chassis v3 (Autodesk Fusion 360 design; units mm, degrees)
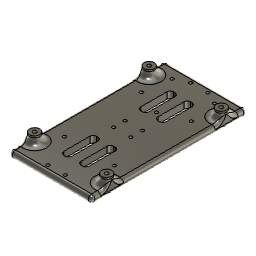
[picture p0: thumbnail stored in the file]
sketch "草图1" plane through (0, 0, 0) normal (0, 0, 1) x axis (1, 0, 0)
  line L1 (-25.25, -47.5) -> (25.25, -47.5)
  line L2 (-25.25, 47.5) -> (-25.25, -47.5)
  line L3 (25.25, 47.5) -> (-25.25, 47.5)
  line L4 (25.25, -47.5) -> (25.25, 47.5)
  line L5 (-25.25, 47.5) -> (25.25, -47.5)
  line L6 (25.25, 47.5) -> (-25.25, -47.5)
  line L7 (-25.25, 0) -> (25.25, 0)
  line L8 (0, -47.5) -> (0, 47.5)
  circle C1 centre (22, 35) radius 1.125
  circle C2 centre (-22, 35) radius 1.125
  circle C3 centre (22, -35) radius 1.125
  circle C4 centre (-22, -35) radius 1.125
  circle C5 centre (-22, 35) radius 2.125
  circle C6 centre (22, 35) radius 2.125
  circle C7 centre (22, -35) radius 2.125
  circle C8 centre (-22, -35) radius 2.125
  circle C9 centre (-22, 35) radius 3.125
  circle C10 centre (22, 35) radius 3.125
  circle C11 centre (22, -35) radius 3.125
  circle C12 centre (-22, -35) radius 3.125
  point P6 (0, 0)
  point P1 (0, 0)
  point P7 (25.25, 0)
  point P8 (-25.25, 0)
  point P9 (0, 47.5)
  point P10 (0, -47.5)
  point P4 (-25.25, 47.5)
  point P5 (25.25, 47.5)
  point P2 (25.25, -47.5)
  point P11 (22, 35)
  point P12 (-22, 35)
  point P13 (22, -35)
  horizontal L1
  perpendicular L1 L2
  parallel L1 L3
  parallel L2 L4
  coincident L5 P6
  coincident L6 P6
  coincident P1 P6
  midpoint L4 P7
  midpoint L2 P8
  midpoint L3 P9
  midpoint L1 P10
  symmetric L8 C1 C2
  symmetric L7 C1 C3
  symmetric L7 C2 C4
  dimension "d9" distance P4 P5 = 50.5
  dimension "d10" distance P2 P5 = 95
  dimension "d11" diameter C1 = 2.25
  dimension "d12" distance P11 P12 = 44
  dimension "d13" distance P11 P13 = 70
  dimension "d26" = 1
  dimension "d27" = 1
  dimension "d28" = 1
  dimension "d29" = 1
  dimension "d30" = 2
  dimension "d31" = 2
  dimension "d32" = 2
  dimension "d33" = 2
extrude "拉伸1" new body sketch "草图1" profile of L1 L2 L3 L4 C1 C2 C3 C4 along normal blind 4
sketch "草图2" plane through (0, 0, 0) normal (0, 0, -1) x axis (1, 0, 0)
  line L1 (25.25, -47.5) -> (-25.25, -47.5)
  line L2 (25.25, 47.5) -> (25.25, -47.5)
  line L3 (-25.25, 47.5) -> (25.25, 47.5)
  line L4 (-25.25, -47.5) -> (-25.25, 47.5)
  line L5 (0, -47.5) -> (0, 47.5)
  line L6 (5.25, 3.5) -> (5.25, 43.5)
  line L7 (15.25, 23.5) -> (5.25, 23.5)
  line L8 (2.75, 13.5) -> (7.75, 13.5)
  line L9 (2.75, 33.5) -> (2.75, 13.5)
  line L10 (7.75, 33.5) -> (2.75, 33.5)
  line L11 (7.75, 13.5) -> (7.75, 33.5)
  line L12 (2.75, 33.5) -> (7.75, 13.5)
  line L13 (7.75, 33.5) -> (2.75, 13.5)
  line L14 (0, 47.5) -> (0, -47.5)
  line L15 (-7.75, 33.5) -> (-2.75, 33.5)
  line L16 (-7.75, 13.5) -> (-7.75, 33.5)
  line L17 (-2.75, 33.5) -> (-2.75, 13.5)
  line L18 (-2.75, 13.5) -> (-7.75, 13.5)
  line L19 (25.25, 0) -> (-25.25, 0)
  line L20 (-2.75, -33.5) -> (-2.75, -13.5)
  line L21 (-7.75, -33.5) -> (-2.75, -33.5)
  line L22 (7.75, -33.5) -> (2.75, -33.5)
  line L23 (7.75, -13.5) -> (7.75, -33.5)
  line L24 (2.75, -33.5) -> (2.75, -13.5)
  line L25 (-7.75, -13.5) -> (-7.75, -33.5)
  line L26 (-2.75, -13.5) -> (-7.75, -13.5)
  line L27 (2.75, -13.5) -> (7.75, -13.5)
  circle C1 centre (22, -35) radius 1.125
  circle C2 centre (-22, -35) radius 1.125
  circle C3 centre (-22, 35) radius 1.125
  circle C4 centre (22, 35) radius 1.125
  circle C5 centre (5.25, 43.5) radius 0.975
  circle C6 centre (5.25, 3.5) radius 0.975
  circle C7 centre (15.25, 23.5) radius 0.975
  circle C8 centre (-5.25, 43.5) radius 0.975
  circle C9 centre (-15.25, 23.5) radius 0.975
  circle C10 centre (-5.25, 3.5) radius 0.975
  circle C11 centre (0, -32.5) radius 15
  circle C12 centre (0, -17.5) radius 0.975
  circle C13 centre (-12.9904, -40) radius 0.975
  circle C14 centre (12.9904, -40) radius 0.975
  circle C15 centre (5.25, -43.5) radius 0.975
  circle C16 centre (15.25, -23.5) radius 0.975
  circle C17 centre (-15.25, -23.5) radius 0.975
  circle C18 centre (-5.25, -43.5) radius 0.975
  circle C19 centre (-5.25, -3.5) radius 0.975
  circle C20 centre (5.25, -3.5) radius 0.975
  point P10 (0, 47.5)
  point P11 (0, -47.5)
  point P12 (5.25, 43.5)
  point P14 (5.25, 43.5)
  point P13 (5.25, 3.5)
  point P15 (5.25, 3.5)
  point P16 (5.25, 23.5)
  point P17 (15.25, 23.5)
  point P18 (15.25, 23.5)
  point P22 (0, -32.5)
  point P23 (0, -17.5)
  point P30 (5.25, 23.5)
  point P26 (7.75, 13.5)
  point P35 (-7.75, 13.5)
  point P27 (2.75, 13.5)
  point P36 (-2.75, 13.5)
  point P28 (2.75, 33.5)
  point P33 (-2.75, 33.5)
  point P29 (7.75, 33.5)
  point P34 (-7.75, 33.5)
  point P37 (-25.25, 0)
  point P38 (25.25, 0)
  point P48 (7.75, -13.5)
  point P49 (2.75, -13.5)
  point P46 (2.75, -33.5)
  point P47 (7.75, -33.5)
  point P44 (-2.75, -33.5)
  point P45 (-7.75, -33.5)
  point P50 (-7.75, -13.5)
  point P43 (-2.75, -13.5)
  midpoint L3 P10
  midpoint L1 P11
  equal C5 C6
  coincident P12 P14
  coincident P13 P15
  parallel L5 L6
  midpoint L6 P16
  perpendicular L6 L7
  coincident P17 P18
  equal C5 C7
  symmetric L5 C5 C8
  symmetric L5 C6 C10
  symmetric L5 C7 C9
  coincident L5 P22
  coincident C11 P23
  coincident L5 P23
  equal C6 C12
  tangent L1 C11
  horizontal L8
  perpendicular L8 L9
  parallel L8 L10
  parallel L9 L11
  coincident L12 P30
  coincident L13 P30
  coincident P16 P30
  symmetric P26 L14 P35
  symmetric P27 L14 P36
  symmetric P28 L14 P33
  symmetric P29 L14 P34
  midpoint L4 P37
  midpoint L2 P38
  symmetric C5 L19 C15
  symmetric C6 L19 C20
  symmetric C7 L19 C16
  symmetric C8 L19 C18
  symmetric C9 L19 C17
  symmetric C10 L19 C19
  symmetric P26 L19 P48
  symmetric P27 L19 P49
  symmetric P28 L19 P46
  symmetric P29 L19 P47
  symmetric P33 L19 P44
  symmetric P34 L19 P45
  symmetric P35 L19 P50
  symmetric P36 L19 P43
  dimension "d12" = 44
  dimension "d16" diameter C5 = 1.95
  dimension "d17" distance P14 P15 = 40
  dimension "d18" distance L3 P12 = 4
  dimension "d19" distance L2 L6 = 20
  dimension "d20" distance P16 P17 = 10
  dimension "d21" diameter C11 = 30
  dimension "d39" distance P26 P29 = 20
  dimension "d40" distance P28 P29 = 5
  dimension "d23" C-Pattern1-Angle = 360
extrude "拉伸2" cut sketch "草图2" profile of C5 C6 C7 C8 C9 C10 C12 C13 C14 L8 L9 L10 L11 L14 L15 L16 L17 L18 C15 C16 C17 L20 L21 L22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 against normal blind 4
extrude "拉伸3" sketch "草图1" profile of C1 C2 C3 C4 C5 C6 C7 C8 C9 C10 C11 C12 blind 5
extrude "拉伸4" cut sketch "草图1" profile of C1 C2 C3 C4 C5 C6 C7 C8 along normal blind 4
fillet "圆角1" radius 4
fillet "圆角2" radius 2
fillet "圆角3" radius 2
fillet "圆角4" radius 2
fillet "圆角5" radius 2
fillet "圆角7" radius 2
